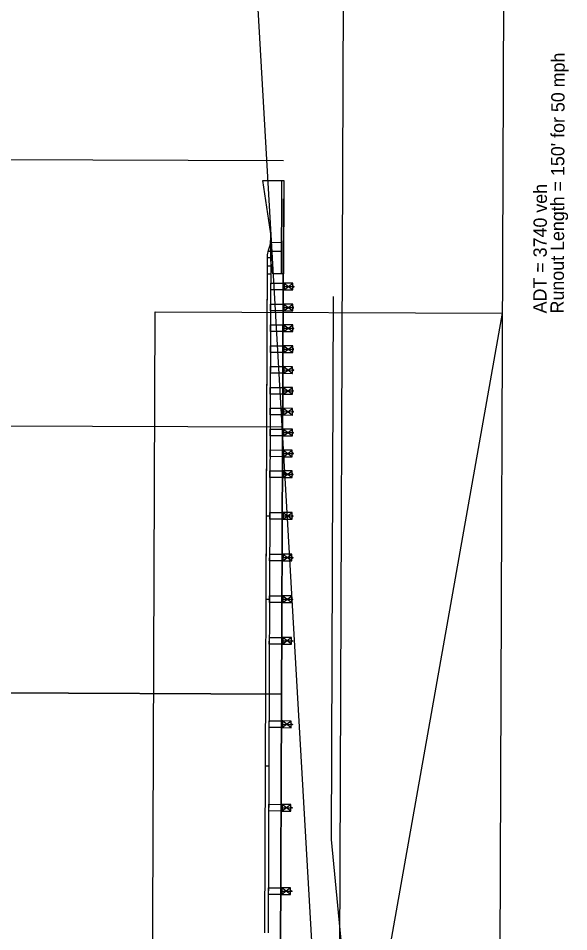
# Model space of a CAD drawing. Extents: x 15359458 to 15360238, y 8797399 to 8799222.
# Drawn here: x 15359934.3 to 15359975.5, y 8798014.5 to 8798083 of the extents above; entities that cross this region are included whole.
import ezdxf

# ---------------------------------------------------------------- set-up
doc = ezdxf.new("R2010")
doc.units = 0
for name, color, linetype in [('_CIVIL_CONSTRUCTION', 7, 'Continuous'), ('Alignment', 7, 'Continuous'), ('MeshTop', 7, 'Continuous'), ('PhoTerrainTriangle', 7, 'Continuous'), ('PhoTerrainVoid', 7, 'Continuous')]:
    doc.layers.add(name, color=color, linetype=linetype)

msp = doc.modelspace()

# ---------------------------------------------------------------- linework, layer by layer
at = {"layer": '_CIVIL_CONSTRUCTION'}
for p, q in [((15359952.585, 8798070.865), (15359954.168, 8798070.859)), ((15359952.585, 8798070.862), (15359952.585, 8798070.865)), ((15359953.195, 8798066.862), (15359952.585, 8798070.862)), ((15359954.001, 8798070.86), (15359953.975, 8798063.86)), ((15359954.168, 8798070.859), (15359954.142, 8798063.86)), ((15359953.187, 8798064.863), (15359953.195, 8798066.862)), ((15359953.193, 8798066.363), (15359953.044, 8798026.968)), ((15359953.166, 8798066.113), (15359953.167, 8798066.363)), ((15359953.984, 8798066.194), (15359953.166, 8798066.197)), ((15359953.193, 8798066.363), (15359953.167, 8798066.363)), ((15359953.981, 8798065.527), (15359952.979, 8798065.531)), ((15359953.012, 8798065.63), (15359953.069, 8798065.773)), ((15359952.917, 8798065.169), (15359952.773, 8798026.969)), ((15359952.917, 8798065.073), (15359952.821, 8798039.469)), ((15359952.917, 8798065.073), (15359953.188, 8798065.072)), ((15359953.35, 8798063.863), (15359953.187, 8798064.863)), ((15359952.915, 8798064.468), (15359953.186, 8798064.467)), ((15359952.913, 8798063.864), (15359953.183, 8798063.863)), ((15359954.142, 8798063.86), (15359953.35, 8798063.863)), ((15359953.179, 8798062.655), (15359953.181, 8798063.155)), ((15359954.178, 8798062.651), (15359953.179, 8798062.655)), ((15359953.181, 8798063.155), (15359954.18, 8798063.151)), ((15359954.18, 8798063.151), (15359954.178, 8798062.651)), ((15359954.178, 8798062.651), (15359954.847, 8798063.149)), ((15359954.179, 8798062.901), (15359954.846, 8798062.899)), ((15359954.18, 8798063.151), (15359954.845, 8798062.649)), ((15359954.845, 8798062.649), (15359954.847, 8798063.149)), ((15359954.846, 8798062.979), (15359954.863, 8798062.979)), ((15359954.846, 8798062.819), (15359954.862, 8798062.819)), ((15359954.862, 8798062.819), (15359954.863, 8798062.979)), ((15359954.862, 8798062.939), (15359954.9, 8798062.938)), ((15359954.862, 8798062.923), (15359954.9, 8798062.922)), ((15359954.862, 8798062.875), (15359954.9, 8798062.874)), ((15359954.862, 8798062.859), (15359954.9, 8798062.858)), ((15359954.9, 8798062.858), (15359954.9, 8798062.938)), ((15359954.9, 8798062.908), (15359954.929, 8798062.908)), ((15359954.9, 8798062.888), (15359954.929, 8798062.888)), ((15359954.929, 8798062.888), (15359954.929, 8798062.908)), ((15359953.173, 8798061.092), (15359953.175, 8798061.592)), ((15359953.175, 8798061.592), (15359954.174, 8798061.588)), ((15359954.174, 8798061.588), (15359954.172, 8798061.089)), ((15359954.172, 8798061.089), (15359954.841, 8798061.586)), ((15359954.173, 8798061.339), (15359954.84, 8798061.336)), ((15359954.174, 8798061.589), (15359954.839, 8798061.086)), ((15359954.839, 8798061.086), (15359954.841, 8798061.586)), ((15359954.84, 8798061.416), (15359954.857, 8798061.416)), ((15359954.84, 8798061.256), (15359954.856, 8798061.256)), ((15359954.856, 8798061.256), (15359954.857, 8798061.416)), ((15359954.856, 8798061.312), (15359954.894, 8798061.312)), ((15359954.856, 8798061.296), (15359954.894, 8798061.296)), ((15359954.857, 8798061.376), (15359954.894, 8798061.376)), ((15359954.857, 8798061.36), (15359954.894, 8798061.36)), ((15359954.894, 8798061.296), (15359954.894, 8798061.376)), ((15359954.894, 8798061.346), (15359954.923, 8798061.346)), ((15359954.894, 8798061.326), (15359954.923, 8798061.326)), ((15359954.923, 8798061.326), (15359954.923, 8798061.346)), ((15359954.172, 8798061.089), (15359953.173, 8798061.092)), ((15359953.167, 8798059.53), (15359953.169, 8798060.03)), ((15359953.169, 8798060.03), (15359954.168, 8798060.026)), ((15359954.168, 8798060.026), (15359954.166, 8798059.526)), ((15359954.166, 8798059.526), (15359954.835, 8798060.024)), ((15359954.168, 8798060.026), (15359954.833, 8798059.524)), ((15359954.833, 8798059.524), (15359954.835, 8798060.024)), ((15359954.834, 8798059.854), (15359954.851, 8798059.854)), ((15359954.85, 8798059.694), (15359954.851, 8798059.854)), ((15359954.166, 8798059.526), (15359953.167, 8798059.53)), ((15359954.167, 8798059.776), (15359954.834, 8798059.774)), ((15359954.834, 8798059.694), (15359954.85, 8798059.694)), ((15359954.85, 8798059.75), (15359954.888, 8798059.749)), ((15359954.85, 8798059.734), (15359954.888, 8798059.733)), ((15359954.851, 8798059.814), (15359954.888, 8798059.813)), ((15359954.851, 8798059.798), (15359954.888, 8798059.797)), ((15359954.888, 8798059.733), (15359954.888, 8798059.813)), ((15359954.888, 8798059.783), (15359954.917, 8798059.783)), ((15359954.888, 8798059.763), (15359954.917, 8798059.763)), ((15359954.917, 8798059.763), (15359954.917, 8798059.783)), ((15359953.161, 8798057.967), (15359953.163, 8798058.467)), ((15359954.161, 8798057.964), (15359953.161, 8798057.967)), ((15359953.163, 8798058.467), (15359954.162, 8798058.463)), ((15359954.162, 8798058.463), (15359954.161, 8798057.964)), ((15359954.161, 8798057.964), (15359954.829, 8798058.461)), ((15359954.161, 8798058.214), (15359954.828, 8798058.211)), ((15359954.162, 8798058.464), (15359954.827, 8798057.961)), ((15359954.827, 8798057.961), (15359954.829, 8798058.461)), ((15359954.828, 8798058.291), (15359954.845, 8798058.291)), ((15359954.828, 8798058.131), (15359954.844, 8798058.131)), ((15359954.844, 8798058.131), (15359954.845, 8798058.291)), ((15359954.844, 8798058.171), (15359954.882, 8798058.171)), ((15359954.845, 8798058.251), (15359954.882, 8798058.251)), ((15359954.845, 8798058.235), (15359954.882, 8798058.235)), ((15359954.845, 8798058.187), (15359954.882, 8798058.187)), ((15359954.882, 8798058.171), (15359954.882, 8798058.251)), ((15359954.882, 8798058.221), (15359954.912, 8798058.221)), ((15359954.882, 8798058.201), (15359954.911, 8798058.201)), ((15359954.911, 8798058.201), (15359954.912, 8798058.221)), ((15359953.155, 8798056.405), (15359953.157, 8798056.905)), ((15359953.157, 8798056.905), (15359954.157, 8798056.901)), ((15359954.157, 8798056.901), (15359954.155, 8798056.401)), ((15359954.155, 8798056.401), (15359954.823, 8798056.899)), ((15359954.156, 8798056.651), (15359954.822, 8798056.649)), ((15359954.157, 8798056.901), (15359954.821, 8798056.399)), ((15359954.821, 8798056.399), (15359954.823, 8798056.899)), ((15359954.822, 8798056.729), (15359954.839, 8798056.729)), ((15359954.822, 8798056.569), (15359954.838, 8798056.569)), ((15359954.838, 8798056.569), (15359954.839, 8798056.729)), ((15359954.839, 8798056.689), (15359954.876, 8798056.689)), ((15359954.839, 8798056.673), (15359954.876, 8798056.673)), ((15359954.839, 8798056.625), (15359954.876, 8798056.625)), ((15359954.839, 8798056.609), (15359954.876, 8798056.609)), ((15359954.876, 8798056.609), (15359954.876, 8798056.689)), ((15359954.876, 8798056.659), (15359954.906, 8798056.658)), ((15359954.876, 8798056.639), (15359954.906, 8798056.638)), ((15359954.906, 8798056.638), (15359954.906, 8798056.658)), ((15359954.155, 8798056.401), (15359953.155, 8798056.405)), ((15359953.149, 8798054.843), (15359953.151, 8798055.342)), ((15359953.151, 8798055.342), (15359954.151, 8798055.338)), ((15359954.151, 8798055.338), (15359954.149, 8798054.839)), ((15359954.149, 8798054.839), (15359954.817, 8798055.336)), ((15359954.15, 8798055.089), (15359954.816, 8798055.086)), ((15359954.151, 8798055.339), (15359954.815, 8798054.836)), ((15359954.815, 8798054.836), (15359954.817, 8798055.336)), ((15359954.817, 8798055.166), (15359954.833, 8798055.166)), ((15359954.833, 8798055.006), (15359954.833, 8798055.166)), ((15359954.833, 8798055.126), (15359954.87, 8798055.126)), ((15359954.833, 8798055.11), (15359954.87, 8798055.11)), ((15359954.833, 8798055.062), (15359954.87, 8798055.062)), ((15359954.87, 8798055.046), (15359954.87, 8798055.126)), ((15359954.87, 8798055.096), (15359954.9, 8798055.096)), ((15359954.87, 8798055.076), (15359954.9, 8798055.076)), ((15359954.9, 8798055.076), (15359954.9, 8798055.096)), ((15359954.149, 8798054.839), (15359953.149, 8798054.843)), ((15359954.816, 8798055.006), (15359954.833, 8798055.006)), ((15359954.833, 8798055.046), (15359954.87, 8798055.046)), ((15359953.143, 8798053.28), (15359953.145, 8798053.78)), ((15359953.145, 8798053.78), (15359954.145, 8798053.776)), ((15359954.145, 8798053.776), (15359954.143, 8798053.276)), ((15359954.143, 8798053.276), (15359954.811, 8798053.774)), ((15359954.145, 8798053.776), (15359954.809, 8798053.274)), ((15359954.809, 8798053.274), (15359954.811, 8798053.774)), ((15359954.143, 8798053.276), (15359953.143, 8798053.28)), ((15359954.144, 8798053.526), (15359954.81, 8798053.524)), ((15359954.81, 8798053.444), (15359954.827, 8798053.444)), ((15359954.811, 8798053.604), (15359954.827, 8798053.604)), ((15359954.827, 8798053.444), (15359954.827, 8798053.604)), ((15359954.827, 8798053.564), (15359954.864, 8798053.564)), ((15359954.827, 8798053.548), (15359954.864, 8798053.548)), ((15359954.827, 8798053.5), (15359954.864, 8798053.5)), ((15359954.827, 8798053.484), (15359954.864, 8798053.484)), ((15359954.864, 8798053.484), (15359954.864, 8798053.564)), ((15359954.864, 8798053.534), (15359954.894, 8798053.533)), ((15359954.864, 8798053.514), (15359954.894, 8798053.513)), ((15359954.894, 8798053.513), (15359954.894, 8798053.533)), ((15359953.137, 8798051.718), (15359953.139, 8798052.217)), ((15359953.137, 8798051.718), (15359953.139, 8798052.217)), ((15359954.137, 8798051.714), (15359953.137, 8798051.718)), ((15359954.137, 8798051.714), (15359953.137, 8798051.718)), ((15359953.139, 8798052.217), (15359954.139, 8798052.214)), ((15359953.139, 8798052.217), (15359954.139, 8798052.214)), ((15359954.139, 8798052.214), (15359954.137, 8798051.714)), ((15359954.139, 8798052.214), (15359954.137, 8798051.714)), ((15359954.137, 8798051.714), (15359954.805, 8798052.211)), ((15359954.138, 8798051.964), (15359954.804, 8798051.961)), ((15359954.139, 8798052.214), (15359954.804, 8798051.711)), ((15359954.804, 8798051.711), (15359954.805, 8798052.211)), ((15359954.804, 8798051.881), (15359954.821, 8798051.881)), ((15359954.805, 8798052.041), (15359954.821, 8798052.041)), ((15359954.821, 8798051.881), (15359954.821, 8798052.041)), ((15359954.821, 8798052.001), (15359954.859, 8798052.001)), ((15359954.821, 8798051.985), (15359954.858, 8798051.985)), ((15359954.821, 8798051.937), (15359954.858, 8798051.937)), ((15359954.821, 8798051.921), (15359954.858, 8798051.921)), ((15359954.858, 8798051.921), (15359954.859, 8798052.001)), ((15359954.858, 8798051.971), (15359954.888, 8798051.971)), ((15359954.858, 8798051.951), (15359954.888, 8798051.951)), ((15359954.888, 8798051.951), (15359954.888, 8798051.971)), ((15359953.132, 8798050.155), (15359953.133, 8798050.655)), ((15359953.133, 8798050.655), (15359954.133, 8798050.651)), ((15359954.133, 8798050.651), (15359954.131, 8798050.151)), ((15359954.131, 8798050.151), (15359954.799, 8798050.649)), ((15359954.132, 8798050.401), (15359954.799, 8798050.399)), ((15359954.133, 8798050.651), (15359954.798, 8798050.149)), ((15359954.798, 8798050.149), (15359954.799, 8798050.649)), ((15359954.798, 8798050.319), (15359954.815, 8798050.319)), ((15359954.799, 8798050.479), (15359954.815, 8798050.479)), ((15359954.815, 8798050.319), (15359954.815, 8798050.479)), ((15359954.815, 8798050.439), (15359954.853, 8798050.439)), ((15359954.815, 8798050.423), (15359954.853, 8798050.423)), ((15359954.815, 8798050.375), (15359954.852, 8798050.375)), ((15359954.815, 8798050.359), (15359954.852, 8798050.359)), ((15359954.852, 8798050.359), (15359954.853, 8798050.439)), ((15359954.852, 8798050.389), (15359954.882, 8798050.388)), ((15359954.853, 8798050.409), (15359954.882, 8798050.408)), ((15359954.882, 8798050.388), (15359954.882, 8798050.408)), ((15359954.131, 8798050.151), (15359953.132, 8798050.155)), ((15359953.126, 8798048.593), (15359953.127, 8798049.092)), ((15359953.127, 8798049.092), (15359954.127, 8798049.089)), ((15359954.127, 8798049.089), (15359954.125, 8798048.589)), ((15359954.125, 8798048.589), (15359954.794, 8798049.086)), ((15359954.127, 8798049.089), (15359954.792, 8798048.586)), ((15359954.792, 8798048.586), (15359954.794, 8798049.086)), ((15359954.793, 8798048.916), (15359954.809, 8798048.916)), ((15359954.809, 8798048.756), (15359954.809, 8798048.916)), ((15359954.125, 8798048.589), (15359953.126, 8798048.593)), ((15359954.126, 8798048.839), (15359954.793, 8798048.836)), ((15359954.792, 8798048.756), (15359954.809, 8798048.756)), ((15359954.809, 8798048.876), (15359954.847, 8798048.876)), ((15359954.809, 8798048.86), (15359954.847, 8798048.86)), ((15359954.809, 8798048.812), (15359954.846, 8798048.812)), ((15359954.809, 8798048.796), (15359954.846, 8798048.796)), ((15359954.846, 8798048.796), (15359954.847, 8798048.876)), ((15359954.847, 8798048.846), (15359954.876, 8798048.846)), ((15359954.847, 8798048.826), (15359954.876, 8798048.826)), ((15359954.876, 8798048.826), (15359954.876, 8798048.846)), ((15359952.844, 8798045.719), (15359953.115, 8798045.718)), ((15359953.114, 8798045.468), (15359953.116, 8798045.967)), ((15359954.113, 8798045.464), (15359953.114, 8798045.468)), ((15359953.116, 8798045.967), (15359954.115, 8798045.964)), ((15359954.115, 8798045.964), (15359954.113, 8798045.464)), ((15359954.113, 8798045.464), (15359954.782, 8798045.961)), ((15359954.114, 8798045.714), (15359954.781, 8798045.711)), ((15359954.115, 8798045.964), (15359954.78, 8798045.461)), ((15359954.78, 8798045.461), (15359954.782, 8798045.961)), ((15359954.781, 8798045.791), (15359954.798, 8798045.791)), ((15359954.781, 8798045.631), (15359954.797, 8798045.631)), ((15359954.797, 8798045.631), (15359954.798, 8798045.791)), ((15359954.797, 8798045.735), (15359954.835, 8798045.735)), ((15359954.797, 8798045.687), (15359954.835, 8798045.687)), ((15359954.797, 8798045.671), (15359954.835, 8798045.671)), ((15359954.798, 8798045.751), (15359954.835, 8798045.751)), ((15359954.835, 8798045.671), (15359954.835, 8798045.751)), ((15359954.835, 8798045.721), (15359954.864, 8798045.721)), ((15359954.835, 8798045.701), (15359954.864, 8798045.701)), ((15359954.864, 8798045.701), (15359954.864, 8798045.721)), ((15359953.102, 8798042.343), (15359953.104, 8798042.842)), ((15359953.104, 8798042.842), (15359954.103, 8798042.839)), ((15359954.103, 8798042.839), (15359954.101, 8798042.339)), ((15359954.101, 8798042.339), (15359954.77, 8798042.836)), ((15359954.103, 8798042.839), (15359954.768, 8798042.336)), ((15359954.768, 8798042.336), (15359954.77, 8798042.836)), ((15359954.101, 8798042.339), (15359953.102, 8798042.343)), ((15359954.102, 8798042.589), (15359954.769, 8798042.586)), ((15359954.769, 8798042.666), (15359954.786, 8798042.666)), ((15359954.769, 8798042.506), (15359954.785, 8798042.506)), ((15359954.785, 8798042.506), (15359954.786, 8798042.666)), ((15359954.785, 8798042.562), (15359954.823, 8798042.562)), ((15359954.785, 8798042.546), (15359954.823, 8798042.546)), ((15359954.786, 8798042.626), (15359954.823, 8798042.626)), ((15359954.786, 8798042.61), (15359954.823, 8798042.61)), ((15359954.823, 8798042.546), (15359954.823, 8798042.626)), ((15359954.823, 8798042.596), (15359954.852, 8798042.596)), ((15359954.823, 8798042.576), (15359954.852, 8798042.576)), ((15359954.852, 8798042.576), (15359954.852, 8798042.596)), ((15359952.82, 8798039.469), (15359953.091, 8798039.468)), ((15359953.09, 8798039.218), (15359953.092, 8798039.717)), ((15359953.092, 8798039.717), (15359954.092, 8798039.714)), ((15359954.092, 8798039.714), (15359954.09, 8798039.214)), ((15359954.09, 8798039.214), (15359954.758, 8798039.711)), ((15359954.091, 8798039.464), (15359954.757, 8798039.461)), ((15359954.092, 8798039.714), (15359954.756, 8798039.211)), ((15359954.756, 8798039.211), (15359954.758, 8798039.711)), ((15359954.757, 8798039.381), (15359954.773, 8798039.381)), ((15359954.758, 8798039.541), (15359954.774, 8798039.541)), ((15359954.773, 8798039.381), (15359954.774, 8798039.541)), ((15359954.774, 8798039.501), (15359954.811, 8798039.501)), ((15359954.774, 8798039.485), (15359954.811, 8798039.485)), ((15359954.774, 8798039.437), (15359954.811, 8798039.437)), ((15359954.774, 8798039.421), (15359954.811, 8798039.421)), ((15359954.811, 8798039.421), (15359954.811, 8798039.501)), ((15359954.811, 8798039.471), (15359954.841, 8798039.471)), ((15359954.811, 8798039.451), (15359954.841, 8798039.451)), ((15359954.841, 8798039.451), (15359954.841, 8798039.471)), ((15359954.09, 8798039.214), (15359953.09, 8798039.218)), ((15359953.078, 8798036.092), (15359953.08, 8798036.593)), ((15359953.08, 8798036.593), (15359954.081, 8798036.589)), ((15359954.081, 8798036.589), (15359954.079, 8798036.088)), ((15359954.748, 8798036.586), (15359954.079, 8798036.089)), ((15359954.746, 8798036.086), (15359954.081, 8798036.589)), ((15359954.079, 8798036.088), (15359953.078, 8798036.092)), ((15359954.08, 8798036.339), (15359954.747, 8798036.336)), ((15359954.844, 8798036.336), (15359954.851, 8798036.336)), ((15359953.055, 8798029.842), (15359953.057, 8798030.343)), ((15359954.056, 8798029.839), (15359953.055, 8798029.842)), ((15359953.057, 8798030.343), (15359954.057, 8798030.339)), ((15359954.057, 8798030.339), (15359954.056, 8798029.839)), ((15359954.724, 8798030.336), (15359954.056, 8798029.839)), ((15359954.056, 8798030.089), (15359954.723, 8798030.086)), ((15359954.722, 8798029.836), (15359954.057, 8798030.339)), ((15359954.82, 8798030.086), (15359954.827, 8798030.086)), ((15359952.773, 8798026.969), (15359952.726, 8798014.469)), ((15359952.773, 8798026.969), (15359953.044, 8798026.968)), ((15359952.773, 8798026.969), (15359953.044, 8798026.968)), ((15359952.773, 8798026.969), (15359953.044, 8798026.968)), ((15359953.044, 8798026.968), (15359952.997, 8798014.468)), ((15359953.031, 8798023.592), (15359953.033, 8798024.093)), ((15359954.032, 8798023.589), (15359953.031, 8798023.592)), ((15359953.033, 8798024.093), (15359954.034, 8798024.089)), ((15359954.034, 8798024.089), (15359954.032, 8798023.589)), ((15359954.7, 8798024.086), (15359954.032, 8798023.589)), ((15359954.033, 8798023.839), (15359954.699, 8798023.836)), ((15359954.699, 8798023.586), (15359954.034, 8798024.089)), ((15359954.797, 8798023.836), (15359954.804, 8798023.836)), ((15359953.007, 8798017.342), (15359953.009, 8798017.843)), ((15359953.009, 8798017.843), (15359954.01, 8798017.839)), ((15359954.01, 8798017.839), (15359954.008, 8798017.339)), ((15359954.677, 8798017.837), (15359954.008, 8798017.339)), ((15359954.009, 8798017.589), (15359954.676, 8798017.587)), ((15359954.675, 8798017.337), (15359954.01, 8798017.839)), ((15359954.773, 8798017.586), (15359954.78, 8798017.586)), ((15359954.008, 8798017.339), (15359953.007, 8798017.342))]:
    msp.add_line(p, q, dxfattribs=at)
for points in [[(15359954.18, 8798063.151), (15359954.178, 8798062.651), (15359954.845, 8798062.649), (15359954.847, 8798063.149)], [(15359954.174, 8798061.589), (15359954.172, 8798061.089), (15359954.839, 8798061.086), (15359954.841, 8798061.586)], [(15359954.168, 8798060.026), (15359954.166, 8798059.526), (15359954.833, 8798059.524), (15359954.835, 8798060.024)], [(15359954.162, 8798058.464), (15359954.161, 8798057.964), (15359954.827, 8798057.961), (15359954.829, 8798058.461)], [(15359954.157, 8798056.901), (15359954.155, 8798056.401), (15359954.821, 8798056.399), (15359954.823, 8798056.899)], [(15359954.151, 8798055.339), (15359954.149, 8798054.839), (15359954.815, 8798054.836), (15359954.817, 8798055.336)], [(15359954.145, 8798053.776), (15359954.143, 8798053.276), (15359954.809, 8798053.274), (15359954.811, 8798053.774)], [(15359954.139, 8798052.214), (15359954.137, 8798051.714), (15359954.804, 8798051.711), (15359954.805, 8798052.211)], [(15359954.133, 8798050.651), (15359954.131, 8798050.151), (15359954.798, 8798050.149), (15359954.799, 8798050.649)], [(15359954.127, 8798049.089), (15359954.125, 8798048.589), (15359954.792, 8798048.586), (15359954.794, 8798049.086)], [(15359954.115, 8798045.964), (15359954.113, 8798045.464), (15359954.78, 8798045.461), (15359954.782, 8798045.961)], [(15359954.103, 8798042.839), (15359954.101, 8798042.339), (15359954.768, 8798042.336), (15359954.77, 8798042.836)], [(15359954.092, 8798039.714), (15359954.09, 8798039.214), (15359954.756, 8798039.211), (15359954.758, 8798039.711)], [(15359954.081, 8798036.589), (15359954.079, 8798036.089), (15359954.746, 8798036.086), (15359954.748, 8798036.586)], [(15359954.057, 8798030.339), (15359954.056, 8798029.839), (15359954.722, 8798029.836), (15359954.724, 8798030.336)], [(15359954.034, 8798024.089), (15359954.032, 8798023.589), (15359954.699, 8798023.586), (15359954.7, 8798024.086)], [(15359954.01, 8798017.839), (15359954.008, 8798017.339), (15359954.675, 8798017.337), (15359954.677, 8798017.837)]]:
    msp.add_lwpolyline(points, close=True, dxfattribs=at)
for points in [[(15359954.747, 8798036.37), (15359954.79, 8798036.37), (15359954.79, 8798036.303), (15359954.747, 8798036.303)], [(15359954.79, 8798036.356), (15359954.844, 8798036.355), (15359954.844, 8798036.317), (15359954.79, 8798036.317)], [(15359954.723, 8798030.12), (15359954.766, 8798030.12), (15359954.766, 8798030.053), (15359954.723, 8798030.053)], [(15359954.766, 8798030.106), (15359954.82, 8798030.105), (15359954.82, 8798030.067), (15359954.766, 8798030.067)], [(15359954.7, 8798023.87), (15359954.743, 8798023.87), (15359954.742, 8798023.803), (15359954.699, 8798023.803)], [(15359954.743, 8798023.856), (15359954.797, 8798023.856), (15359954.797, 8798023.817), (15359954.742, 8798023.817)], [(15359954.676, 8798017.62), (15359954.719, 8798017.62), (15359954.719, 8798017.553), (15359954.676, 8798017.553)], [(15359954.719, 8798017.606), (15359954.773, 8798017.606), (15359954.773, 8798017.567), (15359954.719, 8798017.567)]]:
    msp.add_lwpolyline(points, dxfattribs=at)
for centre, major_axis, start_param, end_param in [((15359951.844, 8798066.33), (0.005, 1.379), 4.300427, 4.558114), ((15359954.412, 8798065.084), (-0.006, -1.542), 4.353641, 4.660842)]:
    msp.add_ellipse(centre, major_axis=major_axis, ratio=0.97085, start_param=start_param, end_param=end_param, dxfattribs=at)
at = {"layer": 'Alignment'}
for p, q in [((15359962.874, 8799211.335), (15359957.014, 8797661.346)), ((15359974.874, 8799211.289), (15359969.014, 8797661.3))]:
    msp.add_line(p, q, dxfattribs=at)
msp.add_lwpolyline([(15359970.525, 8798060.908), (15359943.958, 8797911.007), (15359944.525, 8798061.006)], close=True, dxfattribs=at)
at = {"layer": 'MeshTop'}
msp.add_line((15359957.73, 8798021.449), (15359957.884, 8798062.164), dxfattribs=at)
msp.add_lwpolyline([(15359961.846, 8797948.433), (15359959.945, 8797998.539), (15359957.73, 8798021.449)], dxfattribs=at)
at = {"layer": 'PhoTerrainTriangle'}
msp.add_line((15359928.192, 8798502.036), (15359961.969, 8797913.904), dxfattribs=at)
at = {"layer": 'PhoTerrainVoid'}
for p, q in [((15359910.985, 8798072.516), (15359954.151, 8798072.353)), ((15359954.14, 8798069.47), (15359953.875, 8797999.47)), ((15359953.875, 8797999.47), (15359954.14, 8798069.47)), ((15359953.875, 8797999.47), (15359954.14, 8798069.47)), ((15359954.097, 8798052.36), (15359910.932, 8798052.523)), ((15359954.097, 8798052.36), (15359910.932, 8798052.523)), ((15359910.856, 8798032.523), (15359954.022, 8798032.36)), ((15359954.022, 8798032.36), (15359910.856, 8798032.523))]:
    msp.add_line(p, q, dxfattribs=at)

# ---------------------------------------------------------------- texts
at = {"layer": 'Alignment'}
for s, p in [("Runout Length = 150' for 50 mph", (15359975.144, 8798060.89)), ('ADT = 3740 veh', (15359973.849, 8798060.895))]:
    msp.add_text(s, height=1, rotation=89.7834, dxfattribs=at).set_placement(p)

doc.saveas('drawing.dxf')
